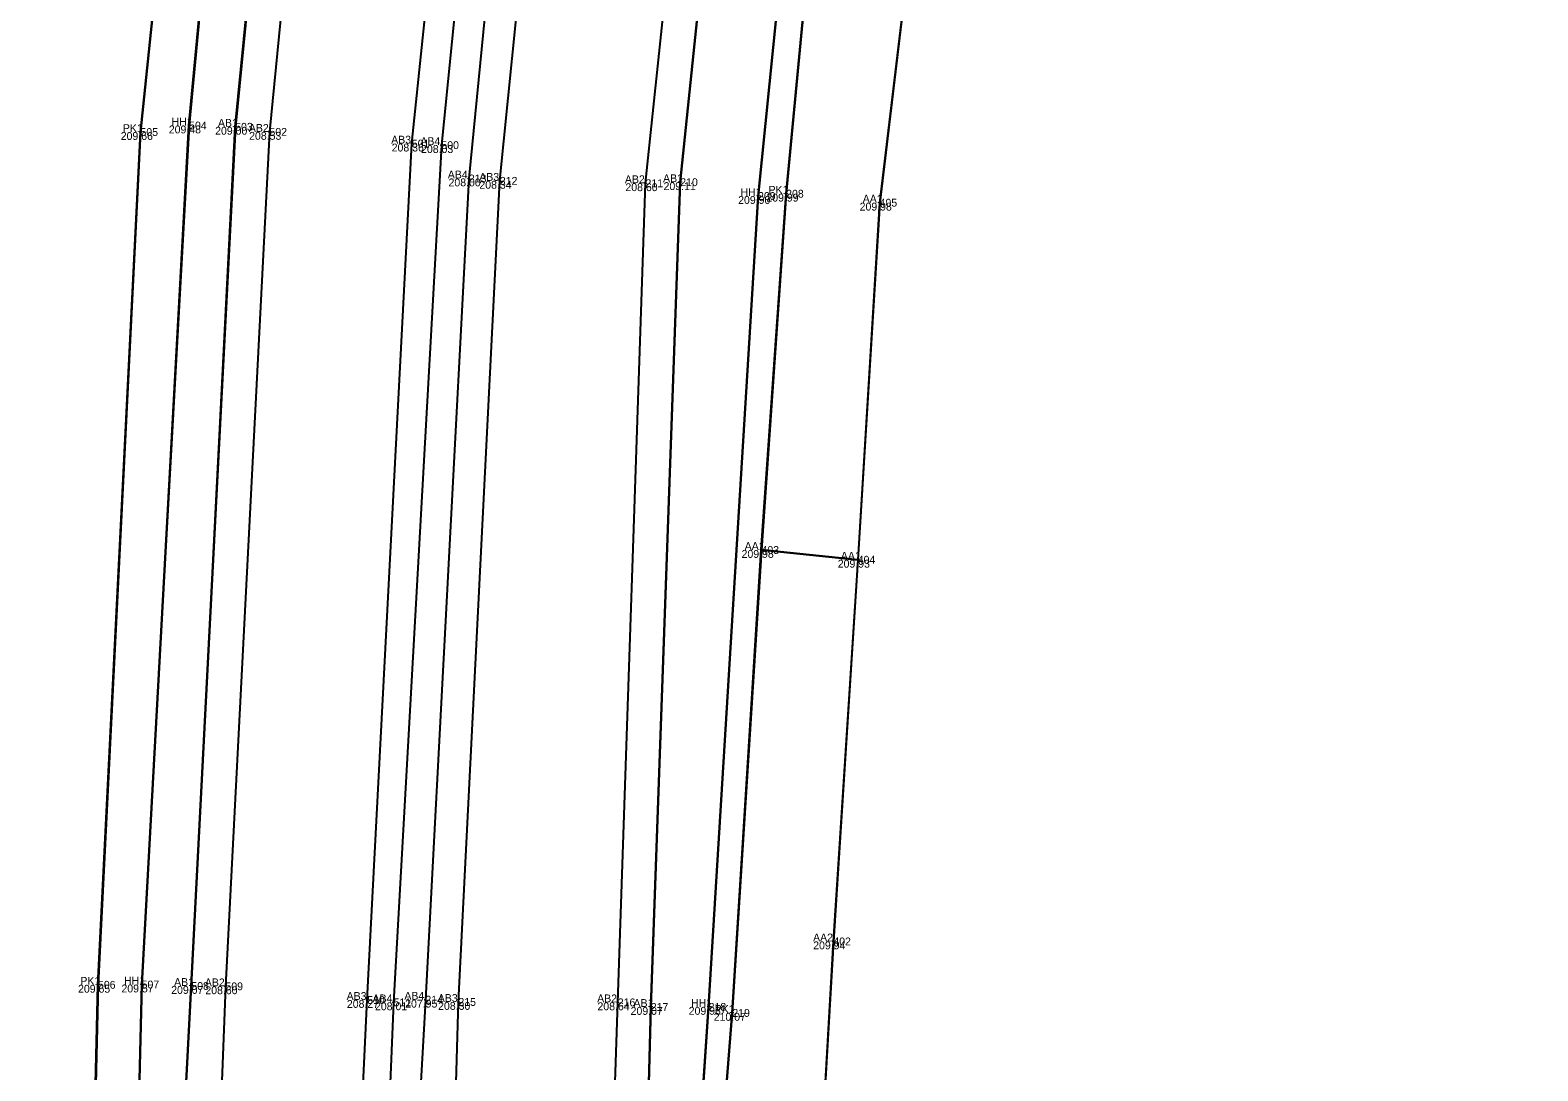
# Model space of a CAD drawing. Extents: x -263091 to -262565, y -1238731 to -1237092.
# Drawn here: x -262835.54 to -262797.21, y -1237908.46 to -1237882.03 of the extents above; entities that cross this region are included whole.
import ezdxf

# ---------------------------------------------------------------- set-up
doc = ezdxf.new("R2010")
doc.units = 0
for name, color, linetype in [('01_Hrana_betónu', 7, 'Continuous'), ('02_Oplotenie', 7, 'Continuous'), ('03_Asfalt', 7, 'Continuous'), ('05_Hrana_terénu', 7, 'Continuous'), ('Groma (21)', 7, 'Continuous'), ('Groma (22)', 7, 'Continuous'), ('Groma (23)', 7, 'Continuous'), ('Groma (24)', 7, 'Continuous'), ('U004_Asfalty', 7, 'Continuous'), ('U004_Betónové_panely', 7, 'Continuous'), ('U004_Zeleň_mimo', 7, 'Continuous'), ('U004_Zeleň_vnútro', 7, 'Continuous'), ('U004_Zeleň_zatrávňovač', 7, 'Continuous')]:
    doc.layers.add(name, color=color, linetype=linetype)

msp = doc.modelspace()

# ---------------------------------------------------------------- linework, layer by layer
at = {"layer": '01_Hrana_betónu'}
for points in [[(-262833.49, -1237932.513), (-262832.358, -1237924.572), (-262831.993, -1237918.626), (-262831.904, -1237915.074), (-262831.439, -1237906.309), (-262830.324, -1237884.482), (-262828.859, -1237869.656), (-262826.973, -1237856.487), (-262824.752, -1237845.872), (-262820.768, -1237827.409), (-262815.971, -1237805.011), (-262811.874, -1237785.528), (-262810.073, -1237767.205), (-262809.465, -1237744.209), (-262809.348, -1237719.32), (-262807.762, -1237709.127), (-262805.583, -1237701.261), (-262801.096, -1237689.829), (-262795.064, -1237676.268)], [(-262794.181, -1237676.612), (-262800.21, -1237690.201), (-262804.735, -1237701.618), (-262806.814, -1237709.415), (-262808.46, -1237719.391), (-262808.589, -1237744.23), (-262809.169, -1237767.262), (-262810.977, -1237785.858), (-262815.119, -1237805.286), (-262819.878, -1237827.449), (-262823.898, -1237846.237), (-262826.14, -1237856.747), (-262827.996, -1237869.725), (-262829.453, -1237884.611), (-262830.572, -1237906.318), (-262830.909, -1237915.064), (-262831.044, -1237918.638), (-262831.379, -1237924.623), (-262832.499, -1237932.636), (-262832.416, -1237932.646)], [(-262828.366, -1237932.946), (-262828.106, -1237929.217), (-262827.649, -1237919.578), (-262827.369, -1237915.073), (-262826.968, -1237906.664), (-262825.835, -1237884.909), (-262824.318, -1237870.338), (-262822.252, -1237856.88), (-262820.394, -1237847.242), (-262816.344, -1237828.005), (-262811.527, -1237806.128), (-262807.485, -1237786.652), (-262805.817, -1237767.526), (-262804.904, -1237743.876), (-262804.544, -1237721.54), (-262802.773, -1237710.111), (-262800.948, -1237703.699), (-262796.578, -1237692.416), (-262790.297, -1237678.834), (-262789.671, -1237677.512)], [(-262788.862, -1237677.903), (-262789.612, -1237679.5), (-262795.758, -1237692.783), (-262800.102, -1237704.105), (-262801.904, -1237710.319), (-262803.638, -1237721.631), (-262804.041, -1237743.855), (-262804.886, -1237767.666), (-262806.567, -1237786.84), (-262810.653, -1237806.707), (-262815.575, -1237828.361), (-262819.614, -1237847.41), (-262821.404, -1237856.927), (-262823.638, -1237870.532), (-262825.083, -1237884.947), (-262826.299, -1237906.725), (-262827.242, -1237929.453), (-262827.527, -1237933.008)], [(-262788.441, -1237678.106), (-262789.499, -1237680.304), (-262796.488, -1237695.789), (-262799.561, -1237704.378), (-262801.599, -1237711.648), (-262803.17, -1237722.277), (-262803.523, -1237744.912), (-262804.331, -1237767.555), (-262806.033, -1237786.907), (-262810.428, -1237808.027), (-262815.321, -1237829.941), (-262818.5, -1237845.545), (-262820.865, -1237857.635), (-262822.962, -1237871.266), (-262824.386, -1237885.795), (-262825.49, -1237906.658), (-262826.835, -1237930.337), (-262826.931, -1237933.053)], [(-262825.987, -1237933.123), (-262825.899, -1237930.36), (-262825.137, -1237919.703), (-262824.89, -1237915.193), (-262824.65, -1237906.715), (-262823.596, -1237885.855), (-262822.137, -1237871.403), (-262820.061, -1237857.781), (-262817.692, -1237845.812), (-262814.459, -1237830.149), (-262809.645, -1237808.205), (-262805.191, -1237787.117), (-262803.484, -1237767.641), (-262802.568, -1237744.998), (-262802.266, -1237722.317), (-262800.862, -1237712.121), (-262798.805, -1237704.616), (-262795.791, -1237696.17), (-262788.393, -1237679.964), (-262787.674, -1237678.477)], [(-262783.803, -1237680.361), (-262791.072, -1237697.733), (-262794.156, -1237706.196), (-262796.111, -1237713.494), (-262797.353, -1237722.795), (-262798.006, -1237745.028), (-262798.995, -1237767.834), (-262800.837, -1237788.066), (-262805.174, -1237808.895), (-262810.048, -1237831.05), (-262813.207, -1237846.368), (-262815.438, -1237858.025), (-262817.519, -1237871.503), (-262819.01, -1237885.889), (-262819.761, -1237906.843), (-262819.991, -1237915.564)], [(-262820.488, -1237916.085), (-262820.893, -1237915.574), (-262820.599, -1237906.725), (-262819.894, -1237885.916), (-262818.364, -1237871.361), (-262816.365, -1237858.042), (-262814.122, -1237846.343), (-262810.891, -1237830.85), (-262806.137, -1237808.69), (-262801.736, -1237787.923), (-262799.952, -1237767.772), (-262798.979, -1237744.912), (-262798.159, -1237722.635), (-262796.927, -1237713.21), (-262795.035, -1237705.927), (-262791.963, -1237697.425), (-262785.076, -1237681.215)]]:
    msp.add_lwpolyline(points, dxfattribs=at)
at = {"layer": '02_Oplotenie'}
for points in [[(-262834.343, -1237921.203), (-262834.024, -1237915.302), (-262833.812, -1237906.279), (-262832.732, -1237884.616), (-262831.151, -1237869.343), (-262829.251, -1237856.325), (-262826.951, -1237845.31), (-262823.094, -1237827.731), (-262817.951, -1237804.339), (-262814.023, -1237784.135), (-262812.336, -1237767.05), (-262811.754, -1237744.594), (-262811.555, -1237719.093), (-262809.863, -1237708.888), (-262807.835, -1237700.632), (-262803.244, -1237689.13), (-262797.291, -1237676.038)], [(-262782.476, -1237683.046), (-262789.338, -1237700.035), (-262791.92, -1237707.468), (-262793.68, -1237714.792), (-262794.853, -1237723.195), (-262795.698, -1237745.299), (-262796.564, -1237768.081), (-262798.719, -1237788.188), (-262802.852, -1237809.448), (-262807.527, -1237831.589), (-262810.764, -1237846.834), (-262812.842, -1237857.763), (-262814.888, -1237871.127), (-262816.319, -1237886.182), (-262816.945, -1237895.233), (-262817.687, -1237906.993), (-262818.366, -1237915.571), (-262818.764, -1237925.136)]]:
    msp.add_lwpolyline(points, dxfattribs=at)
at = {"layer": '03_Asfalt'}
for points in [[(-262777.928, -1237681.411), (-262780.531, -1237687.57), (-262782.281, -1237691.672), (-262786.624, -1237706.531), (-262791.645, -1237746.487), (-262793.969, -1237766.446), (-262796.149, -1237782.824), (-262801.035, -1237810.714), (-262803.747, -1237825.804), (-262807.32, -1237845.566), (-262809.566, -1237858.112), (-262812.403, -1237873.547), (-262813.944, -1237886.41), (-262814.5, -1237895.481), (-262816.945, -1237895.233)], [(-262814.5, -1237895.481), (-262815.119, -1237905.177), (-262816.001, -1237920.483), (-262816.76, -1237934.791)]]:
    msp.add_lwpolyline(points, dxfattribs=at)
at = {"layer": '05_Hrana_terénu'}
for points in [[(-262796.037, -1237675.468), (-262802.307, -1237689.303), (-262806.908, -1237700.928), (-262808.861, -1237708.991), (-262810.491, -1237719.246), (-262810.648, -1237744.371), (-262811.212, -1237767.185), (-262812.78, -1237784.48), (-262817.048, -1237804.549), (-262821.958, -1237827.467), (-262825.893, -1237845.536), (-262828.436, -1237856.363), (-262830.087, -1237869.518), (-262831.495, -1237884.449), (-262832.703, -1237906.272), (-262832.889, -1237914.228), (-262832.974, -1237914.835)], [(-262819.123, -1237925.833), (-262819.193, -1237924.361), (-262818.874, -1237915.472), (-262818.289, -1237906.84), (-262817.033, -1237886.241), (-262815.506, -1237871.209), (-262813.693, -1237857.604), (-262811.493, -1237846.649), (-262808.389, -1237831.401), (-262803.328, -1237809.401), (-262799.108, -1237788.219), (-262797.264, -1237767.972), (-262796.32, -1237745.233), (-262795.609, -1237723.113), (-262794.587, -1237714.488), (-262792.775, -1237707.13), (-262790.198, -1237699.936), (-262783.238, -1237683.427), (-262781.933, -1237681.667), (-262781.499, -1237681.254)]]:
    msp.add_lwpolyline(points, dxfattribs=at)
at = {"layer": 'Groma (21)'}
for centre in [(-262831.495, -1237884.449), (-262832.732, -1237884.616), (-262830.324, -1237884.482), (-262829.453, -1237884.611), (-262825.835, -1237884.909), (-262825.083, -1237884.947), (-262824.386, -1237885.795), (-262823.596, -1237885.855), (-262819.894, -1237885.916), (-262819.01, -1237885.889), (-262817.033, -1237886.241), (-262816.319, -1237886.182), (-262813.944, -1237886.41), (-262816.945, -1237895.233), (-262814.5, -1237895.481), (-262815.119, -1237905.177), (-262833.812, -1237906.279), (-262832.703, -1237906.272), (-262831.439, -1237906.309), (-262830.572, -1237906.318), (-262826.968, -1237906.664), (-262825.49, -1237906.658), (-262826.299, -1237906.725), (-262824.65, -1237906.715), (-262820.599, -1237906.725), (-262819.761, -1237906.843), (-262818.289, -1237906.84), (-262817.687, -1237906.993)]:
    msp.add_circle(centre, 0.01, dxfattribs=at)
at = {"layer": 'U004_Asfalty'}
msp.add_lwpolyline([(-262818.76, -1237925.14), (-262818.37, -1237915.57), (-262817.69, -1237906.99), (-262816.95, -1237895.23), (-262814.5, -1237895.48), (-262815.12, -1237905.18), (-262816, -1237920.48), (-262816.76, -1237934.79), (-262818.3, -1237934.7), (-262817.69, -1237925.58)], close=True, dxfattribs=at)
msp.add_lwpolyline([(-262816.76, -1237934.79), (-262818.3, -1237934.7), (-262817.69, -1237925.58), (-262818.76, -1237925.14), (-262818.37, -1237915.57), (-262817.69, -1237906.99), (-262816.95, -1237895.23), (-262814.5, -1237895.48), (-262815.12, -1237905.18), (-262816, -1237920.48), (-262816.76, -1237934.79)], dxfattribs=at)
at = {"layer": 'U004_Betónové_panely'}
for points in [[(-262796.11, -1237713.49), (-262797.35, -1237722.8), (-262798.01, -1237745.03), (-262799, -1237767.83), (-262800.84, -1237788.07), (-262805.17, -1237808.9), (-262810.05, -1237831.05), (-262813.21, -1237846.37), (-262815.44, -1237858.03), (-262817.52, -1237871.5), (-262819.01, -1237885.89), (-262819.76, -1237906.84), (-262819.99, -1237915.56), (-262820.49, -1237916.09), (-262821.07, -1237925.85), (-262821.58, -1237933.45), (-262821.86, -1237933.43), (-262822, -1237934.47)], [(-262822, -1237934.47), (-262826.02, -1237934.23), (-262826.97, -1237934.17), (-262827.62, -1237934.13), (-262828.45, -1237934.08), (-262832.51, -1237933.84), (-262832.42, -1237932.65), (-262832.5, -1237932.64), (-262833.49, -1237932.51), (-262832.36, -1237924.57), (-262831.99, -1237918.63), (-262831.9, -1237915.07), (-262831.44, -1237906.31), (-262830.32, -1237884.48), (-262828.86, -1237869.66), (-262826.97, -1237856.49), (-262824.75, -1237845.87), (-262820.77, -1237827.41), (-262815.97, -1237805.01), (-262811.87, -1237785.53), (-262810.07, -1237767.21), (-262809.47, -1237744.21), (-262809.35, -1237719.32)], [(-262817.52, -1237871.5), (-262819.01, -1237885.89), (-262819.76, -1237906.84), (-262819.99, -1237915.56), (-262820.49, -1237916.09), (-262821.07, -1237925.85), (-262821.58, -1237933.45), (-262821.86, -1237933.43), (-262822, -1237934.47), (-262826.02, -1237934.23), (-262826.97, -1237934.17), (-262827.62, -1237934.13), (-262828.45, -1237934.08), (-262832.51, -1237933.84), (-262832.42, -1237932.65), (-262832.5, -1237932.64), (-262833.49, -1237932.51), (-262832.36, -1237924.57), (-262831.99, -1237918.63), (-262831.9, -1237915.07), (-262831.44, -1237906.31), (-262830.32, -1237884.48), (-262828.86, -1237869.66)]]:
    msp.add_lwpolyline(points, dxfattribs=at)
at = {"layer": 'U004_Zeleň_mimo'}
for points in [[(-262786.62, -1237706.53), (-262791.65, -1237746.49), (-262793.97, -1237766.45), (-262796.15, -1237782.82), (-262801.03, -1237810.71), (-262803.75, -1237825.8), (-262807.32, -1237845.57), (-262809.57, -1237858.11), (-262812.4, -1237873.55), (-262813.94, -1237886.41), (-262814.5, -1237895.48), (-262816.95, -1237895.23), (-262816.32, -1237886.18), (-262814.89, -1237871.13), (-262812.84, -1237857.76), (-262810.76, -1237846.83), (-262807.53, -1237831.59), (-262802.85, -1237809.45), (-262798.72, -1237788.19), (-262796.56, -1237768.08), (-262795.7, -1237745.3), (-262794.85, -1237723.2), (-262793.68, -1237714.79)], [(-262831.15, -1237869.34), (-262832.73, -1237884.62), (-262833.81, -1237906.28), (-262834.02, -1237915.3), (-262834.34, -1237921.2), (-262833.49, -1237924.81), (-262834.42, -1237925.99), (-262837.15, -1237925.73), (-262837.41, -1237925.56), (-262839.28, -1237924.72), (-262838.95, -1237919.22), (-262848.49, -1237918.39), (-262860.57, -1237917.21), (-262859.39, -1237895.81), (-262865.89, -1237895.46), (-262864.07, -1237848.35)]]:
    msp.add_lwpolyline(points, dxfattribs=at)
at = {"layer": 'U004_Zeleň_vnútro'}
for points in [[(-262819.12, -1237925.83), (-262819.19, -1237924.36), (-262818.87, -1237915.47), (-262818.29, -1237906.84), (-262817.03, -1237886.24), (-262815.51, -1237871.21), (-262813.69, -1237857.6), (-262811.49, -1237846.65), (-262808.39, -1237831.4), (-262803.33, -1237809.4), (-262799.11, -1237788.22), (-262797.26, -1237767.97), (-262796.32, -1237745.23), (-262795.61, -1237723.11), (-262794.59, -1237714.49)], [(-262793.68, -1237714.79), (-262794.85, -1237723.2), (-262795.7, -1237745.3), (-262796.56, -1237768.08), (-262798.72, -1237788.19), (-262802.85, -1237809.45), (-262807.53, -1237831.59), (-262810.76, -1237846.83), (-262812.84, -1237857.76), (-262814.89, -1237871.13), (-262816.32, -1237886.18), (-262816.95, -1237895.23), (-262817.69, -1237906.99), (-262818.37, -1237915.57), (-262818.76, -1237925.14), (-262817.69, -1237925.58), (-262819.12, -1237925.83)], [(-262833.49, -1237924.81), (-262834.34, -1237921.2), (-262834.02, -1237915.3), (-262833.81, -1237906.28), (-262832.73, -1237884.62), (-262831.15, -1237869.34), (-262829.25, -1237856.33), (-262826.95, -1237845.31), (-262823.09, -1237827.73), (-262817.95, -1237804.34), (-262814.02, -1237784.14), (-262812.34, -1237767.05), (-262811.75, -1237744.59), (-262811.56, -1237719.09)], [(-262810.49, -1237719.25), (-262810.65, -1237744.37), (-262811.21, -1237767.19), (-262812.78, -1237784.48), (-262817.05, -1237804.55), (-262821.96, -1237827.47), (-262825.89, -1237845.54), (-262828.44, -1237856.36), (-262830.09, -1237869.52), (-262831.5, -1237884.45), (-262832.7, -1237906.27), (-262832.89, -1237914.23), (-262832.97, -1237914.84), (-262833.88, -1237915.77), (-262833.98, -1237919.36), (-262833.13, -1237919.57), (-262833.49, -1237924.81)], [(-262802.85, -1237809.45), (-262807.53, -1237831.59), (-262810.76, -1237846.83), (-262812.84, -1237857.76), (-262814.89, -1237871.13), (-262816.32, -1237886.18), (-262816.95, -1237895.23), (-262817.69, -1237906.99), (-262818.37, -1237915.57), (-262818.76, -1237925.14), (-262817.69, -1237925.58), (-262819.12, -1237925.83), (-262819.19, -1237924.36), (-262818.87, -1237915.47), (-262818.29, -1237906.84), (-262817.03, -1237886.24), (-262815.51, -1237871.21), (-262813.69, -1237857.6), (-262811.49, -1237846.65), (-262808.39, -1237831.4), (-262803.33, -1237809.4)], [(-262821.96, -1237827.47), (-262825.89, -1237845.54), (-262828.44, -1237856.36), (-262830.09, -1237869.52), (-262831.5, -1237884.45), (-262832.7, -1237906.27), (-262832.89, -1237914.23), (-262832.97, -1237914.84), (-262833.88, -1237915.77), (-262833.98, -1237919.36), (-262833.13, -1237919.57), (-262833.49, -1237924.81), (-262834.34, -1237921.2), (-262834.02, -1237915.3), (-262833.81, -1237906.28), (-262832.73, -1237884.62), (-262831.15, -1237869.34), (-262829.25, -1237856.33), (-262826.95, -1237845.31), (-262823.09, -1237827.73)]]:
    msp.add_lwpolyline(points, dxfattribs=at)
at = {"layer": 'U004_Zeleň_zatrávňovač'}
for points in [[(-262820.84, -1237933.52), (-262821.33, -1237933.48), (-262821.28, -1237933), (-262820.66, -1237925.75), (-262819.99, -1237915.56), (-262819.76, -1237906.84), (-262819.01, -1237885.89), (-262817.52, -1237871.5), (-262815.44, -1237858.03), (-262813.21, -1237846.37), (-262810.05, -1237831.05), (-262805.17, -1237808.9), (-262800.84, -1237788.07), (-262799, -1237767.83), (-262798.01, -1237745.03), (-262797.35, -1237722.8), (-262796.11, -1237713.49)], [(-262794.59, -1237714.49), (-262795.61, -1237723.11), (-262796.32, -1237745.23), (-262797.26, -1237767.97), (-262799.11, -1237788.22), (-262803.33, -1237809.4), (-262808.39, -1237831.4), (-262811.49, -1237846.65), (-262813.69, -1237857.6), (-262815.51, -1237871.21), (-262817.03, -1237886.24), (-262818.29, -1237906.84), (-262818.87, -1237915.47), (-262819.19, -1237924.36), (-262819.12, -1237925.83), (-262819.49, -1237933.29), (-262820.8, -1237933.2), (-262820.84, -1237933.52)], [(-262831.9, -1237915.07), (-262832.97, -1237914.84), (-262832.89, -1237914.23), (-262832.7, -1237906.27), (-262831.5, -1237884.45), (-262830.09, -1237869.52), (-262828.44, -1237856.36), (-262825.89, -1237845.54), (-262821.96, -1237827.47), (-262817.05, -1237804.55), (-262812.78, -1237784.48), (-262811.21, -1237767.19), (-262810.65, -1237744.37), (-262810.49, -1237719.25)], [(-262809.35, -1237719.32), (-262809.47, -1237744.21), (-262810.07, -1237767.21), (-262811.87, -1237785.53), (-262815.97, -1237805.01), (-262820.77, -1237827.41), (-262824.75, -1237845.87), (-262826.97, -1237856.49), (-262828.86, -1237869.66), (-262830.32, -1237884.48), (-262831.44, -1237906.31), (-262831.9, -1237915.07)], [(-262803.33, -1237809.4), (-262808.39, -1237831.4), (-262811.49, -1237846.65), (-262813.69, -1237857.6), (-262815.51, -1237871.21), (-262817.03, -1237886.24), (-262818.29, -1237906.84), (-262818.87, -1237915.47), (-262819.19, -1237924.36), (-262819.12, -1237925.83), (-262819.49, -1237933.29), (-262820.8, -1237933.2), (-262820.84, -1237933.52), (-262821.33, -1237933.48), (-262821.28, -1237933), (-262820.66, -1237925.75), (-262819.99, -1237915.56), (-262819.76, -1237906.84), (-262819.01, -1237885.89), (-262817.52, -1237871.5), (-262815.44, -1237858.03), (-262813.21, -1237846.37), (-262810.05, -1237831.05), (-262805.17, -1237808.9)], [(-262820.77, -1237827.41), (-262824.75, -1237845.87), (-262826.97, -1237856.49), (-262828.86, -1237869.66), (-262830.32, -1237884.48), (-262831.44, -1237906.31), (-262831.9, -1237915.07), (-262832.97, -1237914.84), (-262832.89, -1237914.23), (-262832.7, -1237906.27), (-262831.5, -1237884.45), (-262830.09, -1237869.52), (-262828.44, -1237856.36), (-262825.89, -1237845.54), (-262821.96, -1237827.47)]]:
    msp.add_lwpolyline(points, dxfattribs=at)

# ---------------------------------------------------------------- texts
at = {"layer": 'Groma (22)'}
for s, p in [('504', (-262831.495, -1237884.549)), ('503', (-262830.324, -1237884.582)), ('505', (-262832.732, -1237884.716)), ('502', (-262829.453, -1237884.711)), ('501', (-262825.835, -1237885.009)), ('500', (-262825.083, -1237885.047)), ('213', (-262824.386, -1237885.895)), ('212', (-262823.596, -1237885.955)), ('211', (-262819.894, -1237886.016)), ('210', (-262819.01, -1237885.989)), ('209', (-262817.033, -1237886.341)), ('208', (-262816.319, -1237886.282)), ('405', (-262813.944, -1237886.51)), ('403', (-262816.945, -1237895.333)), ('404', (-262814.5, -1237895.581)), ('402', (-262815.119, -1237905.277)), ('506', (-262833.812, -1237906.379)), ('507', (-262832.703, -1237906.372)), ('508', (-262831.439, -1237906.409)), ('509', (-262830.572, -1237906.418)), ('510', (-262826.968, -1237906.764)), ('511', (-262826.299, -1237906.825)), ('214', (-262825.49, -1237906.758)), ('215', (-262824.65, -1237906.815)), ('216', (-262820.599, -1237906.825)), ('217', (-262819.761, -1237906.943)), ('218', (-262818.289, -1237906.94)), ('219', (-262817.687, -1237907.093))]:
    msp.add_text(s, height=0.2, dxfattribs=at).set_placement(p)
at = {"layer": 'Groma (23)'}
for s, p in [('209.48', (-262832.012, -1237884.649)), ('209.66', (-262833.234, -1237884.816)), ('209.00', (-262830.834, -1237884.682)), ('208.53', (-262829.97, -1237884.811)), ('208.36', (-262826.347, -1237885.109)), ('208.03', (-262825.599, -1237885.147)), ('208.00', (-262824.901, -1237885.995)), ('208.34', (-262824.117, -1237886.055)), ('208.60', (-262820.405, -1237886.116)), ('209.11', (-262819.435, -1237886.089)), ('209.90', (-262817.539, -1237886.441)), ('209.99', (-262816.821, -1237886.382)), ('209.98', (-262814.451, -1237886.61)), ('209.98', (-262817.452, -1237895.433)), ('209.93', (-262815.007, -1237895.681)), ('209.94', (-262815.631, -1237905.377)), ('209.65', (-262834.319, -1237906.479)), ('209.57', (-262833.216, -1237906.472)), ('209.07', (-262831.951, -1237906.509)), ('208.60', (-262831.083, -1237906.518)), ('208.27', (-262827.485, -1237906.864)), ('207.95', (-262826.003, -1237906.858)), ('208.01', (-262826.771, -1237906.925)), ('208.30', (-262825.166, -1237906.915)), ('208.64', (-262821.116, -1237906.925)), ('209.07', (-262820.273, -1237907.043)), ('209.93', (-262818.796, -1237907.04)), ('210.07', (-262818.16, -1237907.193))]:
    msp.add_text(s, height=0.2, dxfattribs=at).set_placement(p)
at = {"layer": 'Groma (24)'}
for s, p in [('PK1', (-262833.179, -1237884.616)), ('HH1', (-262831.942, -1237884.449)), ('AB1', (-262830.762, -1237884.482)), ('AB2', (-262829.977, -1237884.611)), ('AB3', (-262826.359, -1237884.909)), ('AB4', (-262825.617, -1237884.947)), ('AB4', (-262824.92, -1237885.795)), ('AB3', (-262824.12, -1237885.855)), ('AB2', (-262820.418, -1237885.916)), ('AB1', (-262819.448, -1237885.889)), ('PK1', (-262816.766, -1237886.182)), ('HH1', (-262817.48, -1237886.241)), ('AA1', (-262814.372, -1237886.41)), ('AA1', (-262817.373, -1237895.233)), ('AA1', (-262814.928, -1237895.481)), ('AA2', (-262815.634, -1237905.177)), ('PK1', (-262834.259, -1237906.279)), ('HH1', (-262833.15, -1237906.272)), ('AB1', (-262831.877, -1237906.309)), ('AB2', (-262831.096, -1237906.318)), ('AB3', (-262827.492, -1237906.664)), ('AB4', (-262826.833, -1237906.725)), ('AB4', (-262826.024, -1237906.658)), ('AB3', (-262825.174, -1237906.715)), ('AB2', (-262821.123, -1237906.725)), ('AB1', (-262820.199, -1237906.843)), ('HH1', (-262818.736, -1237906.84)), ('PK1', (-262818.134, -1237906.993))]:
    msp.add_text(s, height=0.2, dxfattribs=at).set_placement(p)

doc.saveas('drawing.dxf')
